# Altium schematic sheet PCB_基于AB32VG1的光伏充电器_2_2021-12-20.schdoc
size 309 x 218 mm
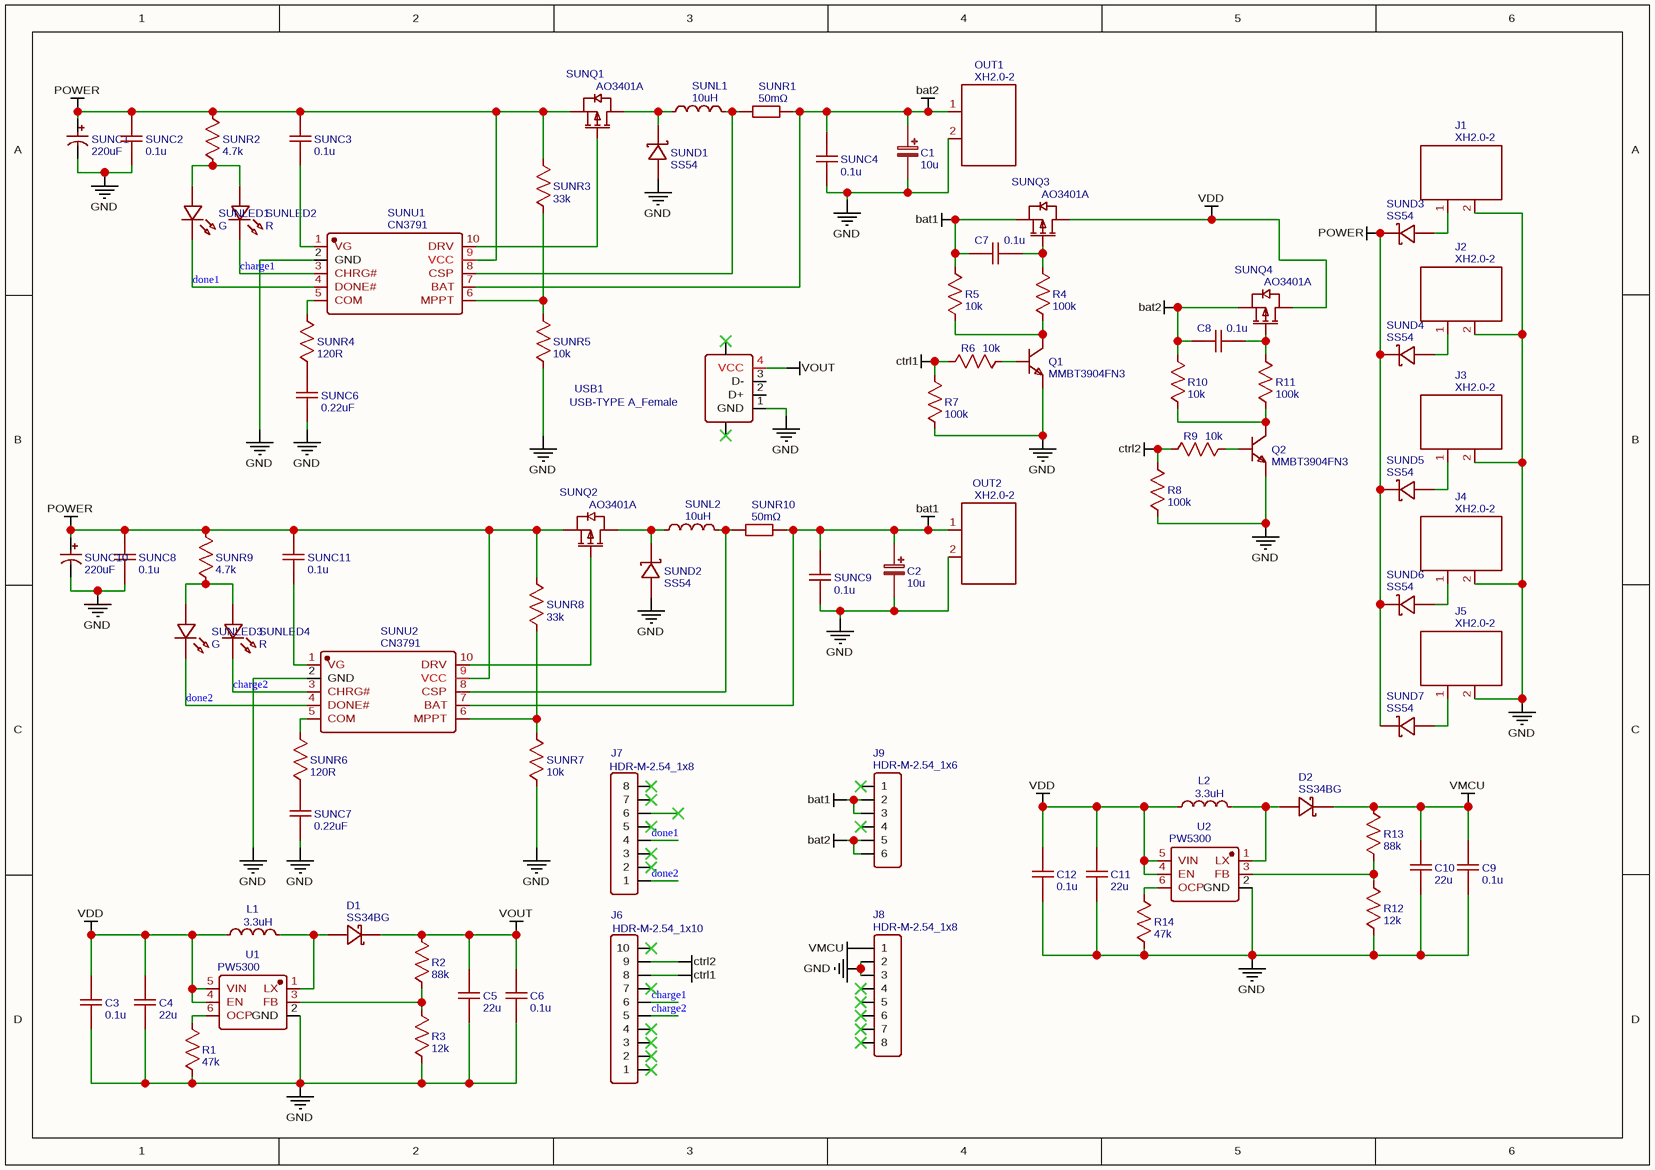
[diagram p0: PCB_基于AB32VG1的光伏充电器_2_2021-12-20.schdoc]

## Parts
C1  10u  [CASE-A_3216]
C2  10u  [CASE-A_3216]
C3  0.1u  [C0805]
C4  22u  [C1206]
C5  22u  [C1206]
C6  0.1u  [C0805]
C7  0.1u  [C0805]
C8  0.1u  [C0805]
C9  0.1u  [C0805]
C10  22u  [C1206]
C11  22u  [C1206]
C12  0.1u  [C0805]
D1  SS34BG  [SMB_L4.6-W3.6-LS5.3-RD]
D2  SS34BG  [SMB_L4.6-W3.6-LS5.3-RD]
J1  XH2.0-2  [XH2.0-2P]
J2  XH2.0-2  [XH2.0-2P]
J3  XH2.0-2  [XH2.0-2P]
J4  XH2.0-2  [XH2.0-2P]
J5  XH2.0-2  [XH2.0-2P]
J6  HDR-M-2.54_1x10  [HDR-M-2.54_1X10]
J7  HDR-M-2.54_1x8  [HDR-M-2.54_1X8]
J8  HDR-M-2.54_1x8  [HDR-M-2.54_1X8]
J9  HDR-M-2.54_1x6  [HDR-M-2.54_1X6]
L1  3.3uH  [IND-SMD_L5.0-W5.0_LQH55DN]
L2  3.3uH  [IND-SMD_L5.0-W5.0_LQH55DN]
OUT1  XH2.0-2  [XH2.0-2P]
OUT2  XH2.0-2  [XH2.0-2P]
Q1  MMBT3904FN3  [DFN-3L_L1.0-W0.6-P0.65-BR]
Q2  MMBT3904FN3  [DFN-3L_L1.0-W0.6-P0.65-BR]
R1  47k  [R0805]
R2  88k  [R0805]
R3  12k  [R0805]
R4  100k  [R0805]
R5  10k  [R0805]
R6  10k  [R0805]
R7  100k  [R0805]
R8  100k  [R0805]
R9  10k  [R0805]
R10  10k  [R0805]
R11  100k  [R0805]
R12  12k  [R0805]
R13  88k  [R0805]
R14  47k  [R0805]
SUNC1  220uF  [CAP-SMD_BD6.3-L6.6-W6.6-FD]
SUNC2  0.1u  [C0603]
SUNC3  0.1u  [C0603]
SUNC4  0.1u  [C0603]
SUNC6  0.22uF  [C0603]
SUNC7  0.22uF  [C0603]
SUNC8  0.1u  [C0603]
SUNC9  0.1u  [C0603]
SUNC10  220uF  [CAP-SMD_BD6.3-L6.6-W6.6-FD]
SUNC11  0.1u  [C0603]
SUND1  SS54  [SMA_L4.4-W2.8-LS5.4-R-RD]
SUND2  SS54  [SMA_L4.4-W2.8-LS5.4-R-RD]
SUND3  SS54  [SMA_L4.4-W2.8-LS5.4-R-RD]
SUND4  SS54  [SMA_L4.4-W2.8-LS5.4-R-RD]
SUND5  SS54  [SMA_L4.4-W2.8-LS5.4-R-RD]
SUND6  SS54  [SMA_L4.4-W2.8-LS5.4-R-RD]
SUND7  SS54  [SMA_L4.4-W2.8-LS5.4-R-RD]
SUNL1  10uH  [IND-SMD_L6.8-W6.8_SMMS0630]
SUNL2  10uH  [IND-SMD_L6.8-W6.8_SMMS0630]
SUNLED1  G  [LED0603_RED]
SUNLED2  R  [LED0603_RED]
SUNLED3  G  [LED0603_RED]
SUNLED4  R  [LED0603_RED]
SUNQ1  AO3401A  [SOT-23_L2.9-W1.3-P0.95-LS2.4-BR]
SUNQ2  AO3401A  [SOT-23_L2.9-W1.3-P0.95-LS2.4-BR]
SUNQ3  AO3401A  [SOT-23_L2.9-W1.3-P0.95-LS2.4-BR]
SUNQ4  AO3401A  [SOT-23_L2.9-W1.3-P0.95-LS2.4-BR]
SUNR1  50mΩ  [R2512]
SUNR2  4.7k  [R0603]
SUNR3  33k  [R0603]
SUNR4  120R  [R0603]
SUNR5  10k  [R0603]
SUNR6  120R  [R0603]
SUNR7  10k  [R0603]
SUNR8  33k  [R0603]
SUNR9  4.7k  [R0603]
SUNR10  50mΩ  [R2512]
SUNU1  CN3791  [SSOP-10_L4.9-W3.9-P1.00-LS6.0-BL]
SUNU2  CN3791  [SSOP-10_L4.9-W3.9-P1.00-LS6.0-BL]
U1  PW5300  [PW5300]
U2  PW5300  [PW5300]
USB1  USB-TYPE A_Female  [USB-A-SMD_USB-M-32]

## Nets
bat1: C2.1 C7.1 J9.2 J9.3 OUT2.1 R5.2 SUNC9.2 SUNQ3.2(S) SUNR10.2 SUNU2.7(BAT)
bat2: C1.1 C8.1 J9.5 J9.6 OUT1.1 R10.2 SUNC4.2 SUNQ4.2(S) SUNR1.2 SUNU1.7(BAT)
ctrl1: J6.8 R6.1 R7.2
ctrl2: J6.9 R8.2 R9.1
GND: C1.2 C2.2 C3.1 C4.1 C5.1 C6.1 C9.1 C10.1 C11.1 C12.1 J1.2 J2.2 J3.2 J4.2 J5.2 J8.2 J8.3 OUT1.2 OUT2.2 Q1.2(E) Q2.2(E) R1.1 R3.1 R7.1 R8.1 R12.1 R14.1 SUNC1.2 SUNC2.1 SUNC4.1 SUNC6.1 SUNC7.1 SUNC8.1 SUNC9.1 SUNC10.2 SUND1.1(A) SUND2.1(A) SUNR5.1 SUNR7.1 SUNU1.2(GND) SUNU2.2(GND) U1.2(GND) U2.2(GND) USB1.1(GND)
POWER: SUNC1.1 SUNC2.2 SUNC3.2 SUNC8.2 SUNC10.1 SUNC11.2 SUND3.2(K) SUND4.2(K) SUND5.2(K) SUND6.2(K) SUND7.2(K) SUNQ1.2(S) SUNQ2.2(S) SUNR2.2 SUNR3.2 SUNR8.2 SUNR9.2 SUNU1.9(VCC) SUNU2.9(VCC)
VDD: C3.2 C4.2 C11.2 C12.2 L1.1 L2.1 SUNQ3.3(D) SUNQ4.3(D) U1.4(EN) U1.5(VIN) U2.4(EN) U2.5(VIN)
VMCU: C9.2 C10.2 D2.1(K) J8.1 R13.2
VOUT: C5.2 C6.2 D1.1(K) R2.2 USB1.4(VCC)
charge1: J6.6 SUNLED2.2 SUNU1.3(CHRG#)
charge2: J6.5 SUNLED4.2 SUNU2.3(CHRG#)
done1: J7.4 SUNLED1.2 SUNU1.4(DONE#)
done2: J7.1 SUNLED3.2 SUNU2.4(DONE#)
NetC7_2: C7.2 R4.2 SUNQ3.1(G)
NetC8_2: C8.2 R11.2 SUNQ4.1(G)
NetD1_2: D1.2(A) L1.2 U1.1(LX)
NetD2_2: D2.2(A) L2.2 U2.1(LX)
NetJ1_1: J1.1 SUND3.1(A)
NetJ2_1: J2.1 SUND4.1(A)
NetJ3_1: J3.1 SUND5.1(A)
NetJ4_1: J4.1 SUND6.1(A)
NetJ5_1: J5.1 SUND7.1(A)
NetQ1_1: Q1.1(B) R6.2
NetQ1_3: Q1.3(C) R4.1 R5.1
NetQ2_1: Q2.1(B) R9.2
NetQ2_3: Q2.3(C) R10.1 R11.1
NetR1_2: R1.2 U1.6(OCP)
NetR2_1: R2.1 R3.2 U1.3(FB)
NetR12_2: R12.2 R13.1 U2.3(FB)
NetR14_2: R14.2 U2.6(OCP)
NetSUNC3_1: SUNC3.1 SUNU1.1(VG)
NetSUNC6_2: SUNC6.2 SUNR4.2
NetSUNC7_2: SUNC7.2 SUNR6.2
NetSUNC11_1: SUNC11.1 SUNU2.1(VG)
NetSUND1_2: SUND1.2(K) SUNL1.1 SUNQ1.3(D)
NetSUND2_2: SUND2.2(K) SUNL2.1 SUNQ2.3(D)
NetSUNL1_2: SUNL1.2 SUNR1.1 SUNU1.8(CSP)
NetSUNL2_2: SUNL2.2 SUNR10.1 SUNU2.8(CSP)
NetSUNLED1_1: SUNLED1.1 SUNLED2.1 SUNR2.1
NetSUNLED3_1: SUNLED3.1 SUNLED4.1 SUNR9.1
NetSUNQ1_1: SUNQ1.1(G) SUNU1.10(DRV)
NetSUNQ2_1: SUNQ2.1(G) SUNU2.10(DRV)
NetSUNR3_1: SUNR3.1 SUNR5.2 SUNU1.6(MPPT)
NetSUNR4_1: SUNR4.1 SUNU1.5(COM)
NetSUNR6_1: SUNR6.1 SUNU2.5(COM)
NetSUNR7_2: SUNR7.2 SUNR8.1 SUNU2.6(MPPT)

Not connected (* = marked no-connect by the designer): J6 1* 2* 3* 4* 7* 10*; J7 2* 3* 5* 6* 7* 8*; J8 4* 5* 6* 7* 8*; J9 1* 4*; USB1 2(D+) 3(D-) 5* 6*

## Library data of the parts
C1 C2 = 10u: nameAlias: Value(F); Contributor: LCEDA_Lib
C3 C6-C9 C12 SUNC2-SUNC4 SUNC8 SUNC9 SUNC11 = 0.1u: nameAlias: Value(F); Contributor: LCEDA_Lib
C4 C5 C10 C11 = 22u: nameAlias: Value(F); Contributor: LCEDA_Lib
D1 D2 = SS34BG: BOM_Manufacturer: Shikues; Contributor: LCSC
J1-J5 OUT1 OUT2 = XH2.0-2: BOM_Manufacturer: EasyEDA; BOM_Manufacturer Part: XH2.54-2A; BOM_EasyEDA: E26521; Contributor: enhed
J6 = HDR-M-2.54_1x10: Contributor: LCEDA_Lib
J7 J8 = HDR-M-2.54_1x8: Contributor: LCEDA_Lib
J9 = HDR-M-2.54_1x6: Contributor: LCEDA_Lib
L1 L2 = 3.3uH: BOM_Manufacturer: Sunlord; BOM_Manufacturer Part: SWPA5040S3R3MT; nameAlias: Inductance
Q1 Q2 = MMBT3904FN3: BOM_Manufacturer: PANJIT International; Contributor: LCSC
R1 R14 = 47k: nameAlias: Value(Ω); Contributor: LCEDA_Lib
R2 R13 = 88k: nameAlias: Value(Ω); Contributor: LCEDA_Lib
R3 R12 = 12k: nameAlias: Value(Ω); Contributor: LCEDA_Lib
R4 R7 R8 R11 = 100k: nameAlias: Value(Ω); Contributor: LCEDA_Lib
R5 R6 R9 R10 = 10k: nameAlias: Value(Ω); Contributor: LCEDA_Lib
SUNC1 SUNC10 = 220uF: BOM_Manufacturer: HONOR; BOM_Manufacturer Part: RVT1A221M0605; nameAlias: Capacitance
SUNC6 SUNC7 = 0.22uF: BOM_Manufacturer: YAGEO; BOM_Manufacturer Part: AC0805KKX7R7BB225; nameAlias: Capacitance; Contributor: LCSC
SUND1-SUND7 = SS54: BOM_Manufacturer: MDD; SMT Type: Basic
SUNL1 SUNL2 = 10uH: BOM_Manufacturer: SXN; BOM_Manufacturer Part: SMMS0630-100M; nameAlias: Inductance
SUNLED1 SUNLED3 = G: BOM_Manufacturer: EVERLIGHT(台湾亿光); BOM_Manufacturer Part: 19-217/R6C-AL1M2VY/3T; Contributor: LCEDA_01
SUNLED2 SUNLED4 = R: BOM_Manufacturer: EVERLIGHT(台湾亿光); BOM_Manufacturer Part: 19-217/R6C-AL1M2VY/3T; Contributor: LCEDA_01
SUNQ1-SUNQ4 = AO3401A: BOM_Manufacturer: Youtai Semiconductor Co., Ltd.; Contributor: LCSC
SUNR1 SUNR10 = 50mΩ: BOM_Manufacturer: KOA Speer Elec; BOM_Manufacturer Part: SR732ETTDR120F; nameAlias: Resistance (Ohms); Contributor: LCSC
SUNR2 SUNR9 = 4.7k: nameAlias: Value(Ω)
SUNR3 SUNR8 = 33k: nameAlias: Value(Ω)
SUNR4 SUNR6 = 120R: nameAlias: Value(Ω)
SUNR5 SUNR7 = 10k: nameAlias: Value(Ω)
SUNU1 SUNU2 = CN3791: BOM_Manufacturer: ShangHai Consonance Elec; Contributor: LCSC; SMT Type: Extend
U1 U2 = PW5300: Contributor: lll777
USB1 = USB-TYPE A_Female: BOM_Manufacturer: ValuePro; Contributor: LCEDA_Lib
